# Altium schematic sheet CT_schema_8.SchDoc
size 371 x 243 mm
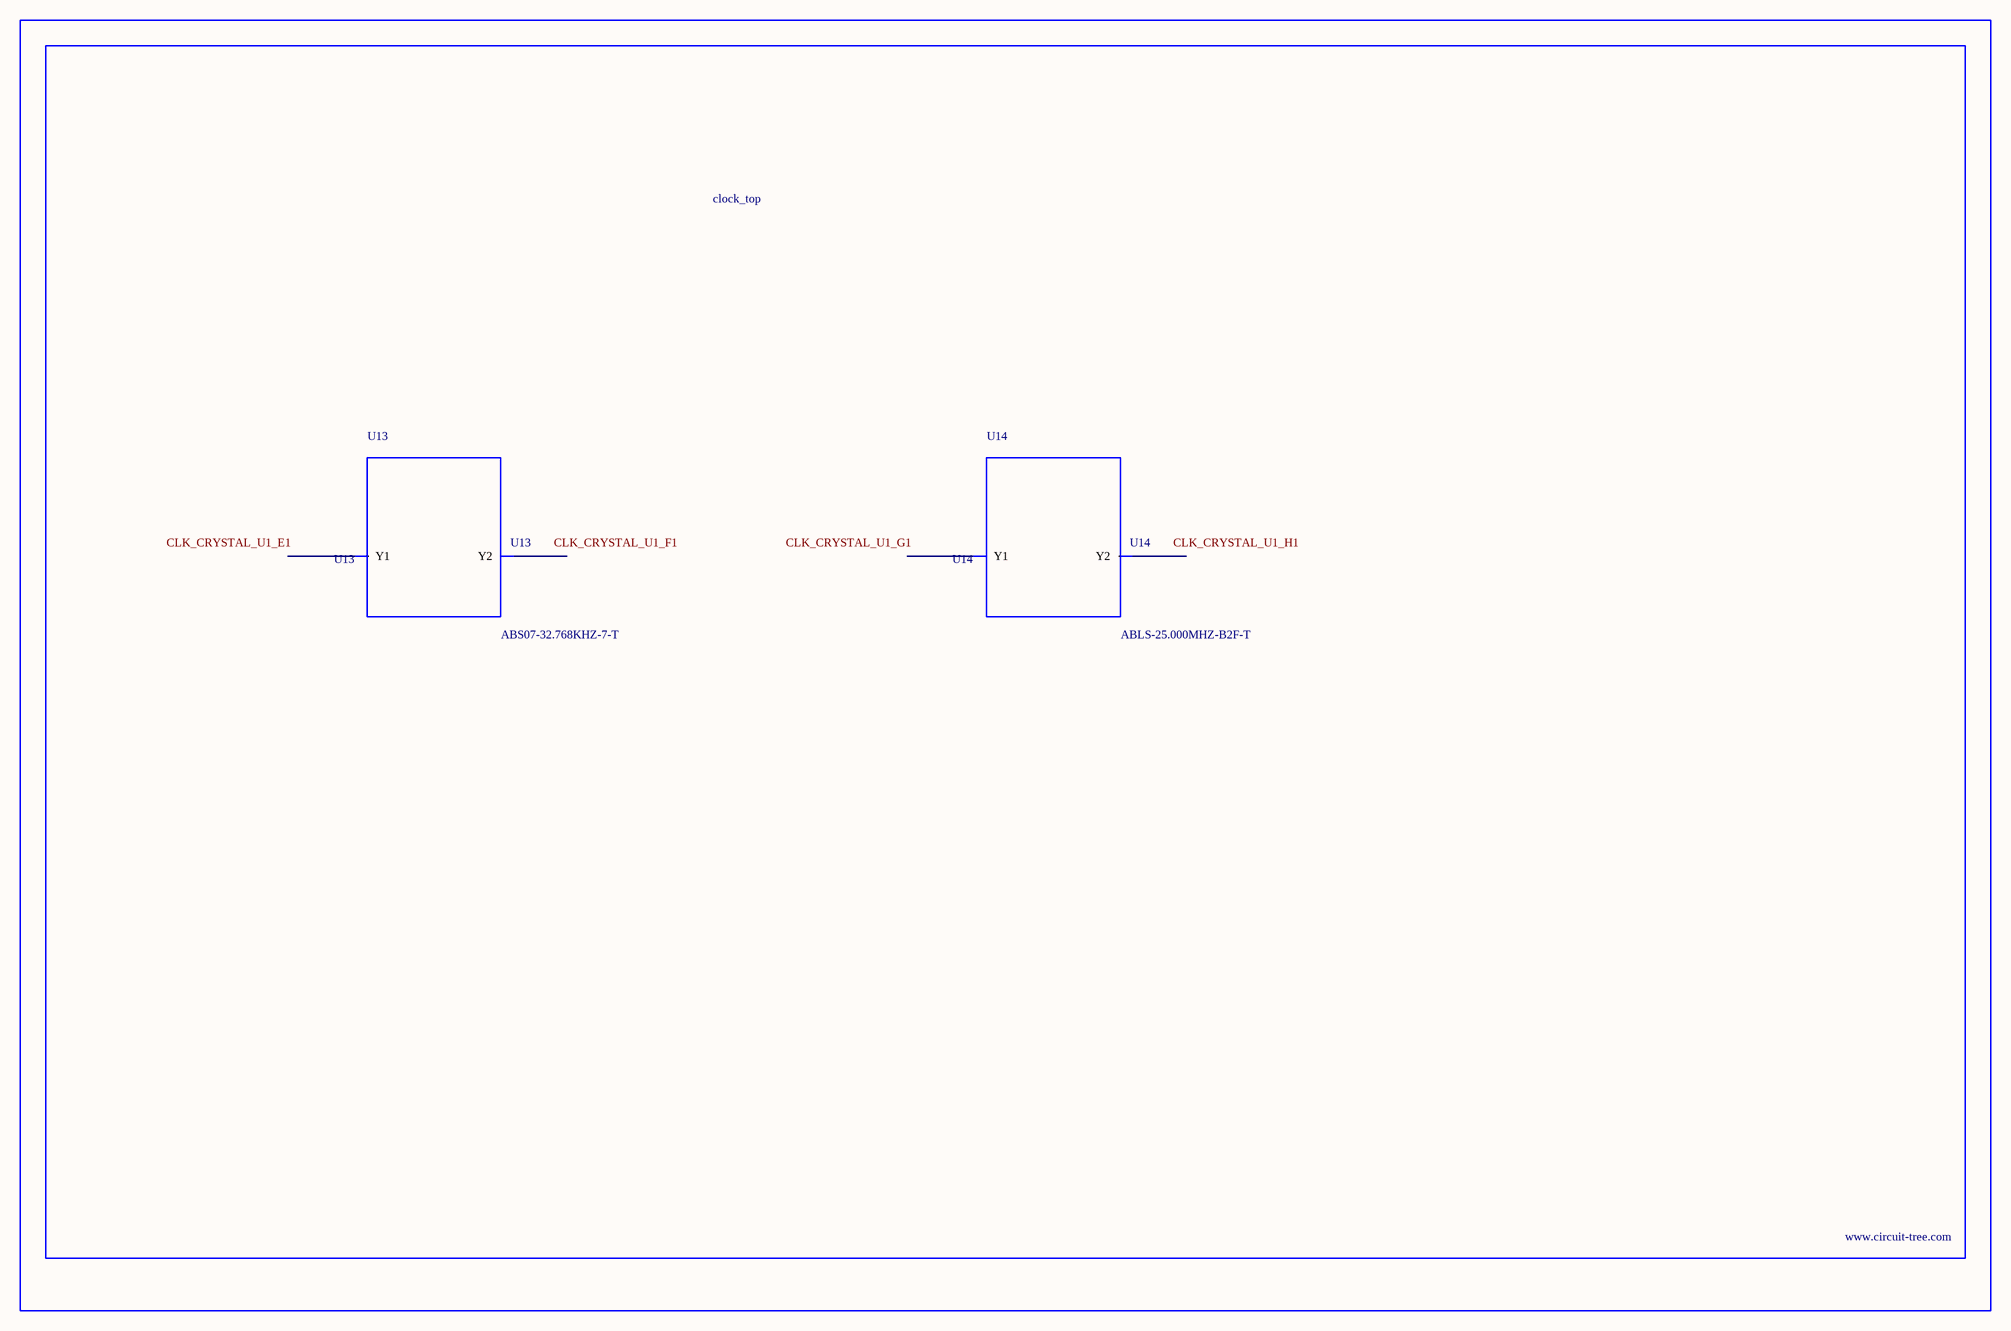
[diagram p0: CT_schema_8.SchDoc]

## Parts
BORDER7  (no value)
U13  ABS07-32.768KHZ-7-T  [ABS07-32.768KHZ-7-T]
U14  ABLS-25.000MHZ-B2F-T  [ABLS-25.000MHZ-B2F-T]

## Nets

Not connected (* = marked no-connect by the designer): U13 1(Y1) 2(Y2); U14 1(Y1) 2(Y2)

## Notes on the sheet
- Labels drawn without touching a wire or pin: CLK_CRYSTAL_U1_E1, CLK_CRYSTAL_U1_F1, CLK_CRYSTAL_U1_G1, CLK_CRYSTAL_U1_H1

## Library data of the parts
BORDER7 = BORDER_PAGE7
